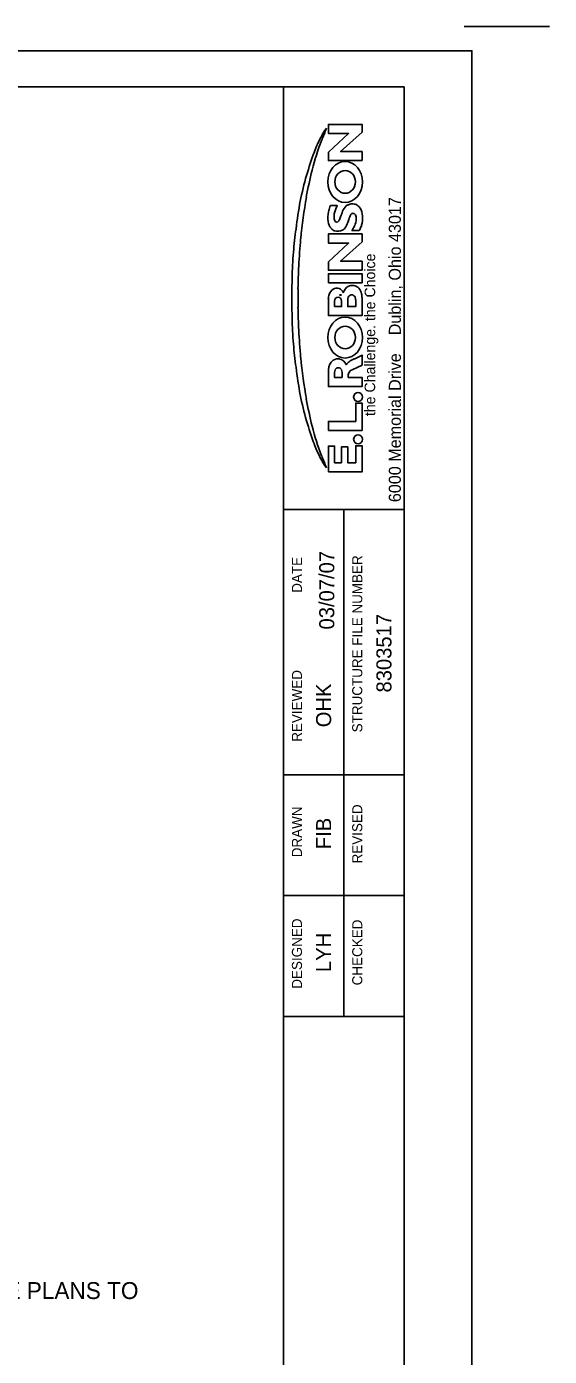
# Model space of a CAD drawing. Extents: x -70.8 to -34.9, y -11.1 to 10.9.
# Drawn here: x -39.19 to -34.86, y -0.16 to 10.86 of the extents above; entities that cross this region are included whole.
import ezdxf

# ---------------------------------------------------------------- set-up
doc = ezdxf.new("R2010")
doc.units = 0
for name, color, linetype in [('Default', 7, 'Continuous'), ('SH_Border', 7, 'Continuous'), ('SH_Cut_Line', 7, 'Continuous'), ('SH_Data', 7, 'Continuous')]:
    doc.layers.add(name, color=color, linetype=linetype)

msp = doc.modelspace()

# ---------------------------------------------------------------- linework, layer by layer
at = {"layer": 'Default'}
for p, q in [((-36.433, 9.166), (-36.494, 9.166)), ((-36.494, 9.166), (-36.433, 9.166)), ((-36.689, 8.462), (-36.689, 8.597)), ((-36.41, 8.612), (-36.41, 8.462)), ((-36.638, 8.583), (-36.638, 8.537)), ((-36.638, 8.537), (-36.638, 8.583)), ((-36.41, 8.462), (-36.689, 8.462)), ((-36.41, 8.052), (-36.492, 8.013)), ((-36.492, 8.013), (-36.41, 8.052)), ((-36.639, 7.992), (-36.639, 7.949)), ((-36.639, 7.949), (-36.639, 7.992)), ((-36.639, 7.949), (-36.575, 7.949)), ((-36.575, 7.949), (-36.639, 7.949)), ((-36.575, 7.949), (-36.575, 7.992)), ((-36.575, 7.992), (-36.575, 7.949))]:
    msp.add_line(p, q, dxfattribs=at)
for points in [[(-36.41, 9.746), (-36.689, 9.746), (-36.689, 9.815), (-36.521, 9.971), (-36.689, 9.971), (-36.689, 10.046), (-36.41, 10.046), (-36.41, 9.981), (-36.588, 9.82), (-36.41, 9.82)], [(-36.41, 8.838), (-36.689, 8.838), (-36.689, 8.907), (-36.521, 9.063), (-36.689, 9.063), (-36.689, 9.138), (-36.41, 9.138), (-36.41, 9.073), (-36.588, 8.912), (-36.41, 8.912)], [(-36.689, 8.734), (-36.689, 8.808), (-36.41, 8.808), (-36.41, 8.734)], [(-36.689, 7.167), (-36.689, 7.381), (-36.638, 7.381), (-36.638, 7.242), (-36.581, 7.242), (-36.581, 7.374), (-36.529, 7.374), (-36.529, 7.242), (-36.462, 7.242), (-36.462, 7.384), (-36.41, 7.384), (-36.41, 7.167)]]:
    msp.add_lwpolyline(points, close=True, dxfattribs=at)
for points in [[(-36.671, 9.373), (-36.616, 9.373), (-36.627, 9.346)], [(-36.627, 9.346), (-36.616, 9.373), (-36.671, 9.373)], [(-36.41, 8.612), (-36.41, 8.462), (-36.689, 8.462), (-36.689, 8.597)], [(-36.689, 8.597), (-36.689, 8.462), (-36.41, 8.462)], [(-36.41, 8.462), (-36.41, 8.612)], [(-36.638, 8.537), (-36.579, 8.537), (-36.579, 8.583)], [(-36.579, 8.583), (-36.579, 8.537), (-36.638, 8.537)], [(-36.528, 8.592), (-36.528, 8.537), (-36.462, 8.537), (-36.462, 8.592)], [(-36.462, 8.592), (-36.462, 8.537), (-36.528, 8.537), (-36.528, 8.592)], [(-36.475, 8.102), (-36.41, 8.134), (-36.41, 8.052)], [(-36.41, 8.052), (-36.41, 8.134), (-36.475, 8.102)], [(-36.524, 7.971), (-36.524, 7.949), (-36.41, 7.949), (-36.41, 7.874), (-36.689, 7.874), (-36.689, 7.949), (-36.689, 8.013)], [(-36.689, 8.013), (-36.689, 7.949), (-36.689, 7.874), (-36.41, 7.874)], [(-36.639, 7.992), (-36.639, 7.949), (-36.575, 7.949), (-36.575, 7.992)], [(-36.41, 7.874), (-36.41, 7.949), (-36.524, 7.949), (-36.524, 7.971)], [(-36.689, 7.51), (-36.689, 7.585), (-36.462, 7.585), (-36.462, 7.737), (-36.41, 7.737), (-36.41, 7.51), (-36.689, 7.51)], [(-36.41, 7.737), (-36.462, 7.737), (-36.462, 7.585), (-36.689, 7.585), (-36.689, 7.51)], [(-36.689, 7.51), (-36.41, 7.51), (-36.41, 7.737)]]:
    msp.add_lwpolyline(points, dxfattribs=at)
for centre, major_axis, ratio, start_param, end_param in [((-35.926, 9.339), (0, 1.141), 0.85, 0.988431, 1.105191), ((-35.926, 9.339), (0, 1.141), 0.85, 0.988431, 1.105191), ((-75.191, 31.113), (0, 49.953), 0.85, 4.274094, 4.276309), ((-75.191, 31.113), (0, 49.953), 0.85, 4.274094, 4.276309), ((-36.479, 9.767), (0, 0.363), 0.85, 0.822588, 0.988431), ((-36.479, 9.767), (0, 0.363), 0.85, 0.822588, 0.988431), ((-34.374, 8.593), (0, 3.112), 0.85, 1.165908, 1.233316), ((-34.374, 8.593), (0, 3.112), 0.85, 1.165908, 1.233316), ((-35.448, 9.198), (0, 1.685), 0.85, 1.132502, 1.288747), ((-35.448, 9.198), (0, 1.685), 0.85, 1.132502, 1.288747), ((-36.35, 9.589), (0, 0.583), 0.85, 1.105191, 1.165908), ((-36.35, 9.589), (0, 0.583), 0.85, 1.105191, 1.165908), ((-35.165, 8.941), (0, 2.119), 0.85, 1.243005, 1.347881), ((-35.165, 8.941), (0, 2.119), 0.85, 1.243005, 1.347881), ((-33.95, 8.688), (0, 3.52), 0.85, 1.288747, 1.354281), ((-33.95, 8.688), (0, 3.52), 0.85, 1.288747, 1.354281), ((-36.55, 9.569), (0, -0.0938), 0.910305, 4.71238898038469, 4.712389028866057), ((-33.976, 8.671), (0, 3.544), 0.85, 1.360764, 1.426378), ((-33.976, 8.671), (0, 3.544), 0.85, 1.360764, 1.426378), ((-32.731, 8.494), (0, 4.963), 0.85, 1.378198, 1.448475), ((-32.731, 8.494), (0, 4.963), 0.85, 1.378198, 1.448475), ((-36.81, 9.44), (0, 0.176), 0.85, 4.250261, 4.3216), ((-36.81, 9.44), (0, 0.176), 0.85, 4.250261, 4.3216), ((-36.486, 9.281), (0, 0.11), 0.85, 0.486829, 1.030221), ((-36.486, 9.281), (0, 0.11), 0.85, 0.486829, 1.030221), ((-36.55, 9.569), (0, -0.17), 0.841969, 0, 4.84813681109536e-08), ((-36.499, 9.31), (0, 0.0761), 0.85, 0.083326, 0.486829), ((-36.499, 9.31), (0, 0.0761), 0.85, 0.083326, 0.486829), ((-36.493, 9.233), (0, 0.154), 0.85, 6.083659, 6.366511), ((-36.493, 9.233), (0, 0.154), 0.85, 6.083659, 6.366511), ((-36.48, 9.311), (0, 0.0741), 0.85, 5.529173, 6.083659), ((-36.48, 9.311), (0, 0.0741), 0.85, 5.529173, 6.083659), ((-36.5, 9.286), (0, 0.109), 0.85, 4.887723, 5.529173), ((-36.5, 9.286), (0, 0.109), 0.85, 4.887723, 5.529174), ((-36.532, 9.273), (0, 0.19), 0.85, 1.320154, 1.737094), ((-36.532, 9.273), (0, 0.19), 0.85, 1.320154, 1.737094), ((-36.519, 9.27), (0, 0.206), 0.85, 1.108668, 1.320154), ((-36.519, 9.27), (0, 0.206), 0.85, 1.108668, 1.320154), ((-36.547, 9.282), (0, 0.111), 0.85, 1.456901, 1.818883), ((-36.547, 9.282), (0, 0.111), 0.85, 1.456901, 1.818883), ((-36.544, 9.282), (0, 0.115), 0.85, 1.297264, 1.456901), ((-36.544, 9.282), (0, 0.115), 0.85, 1.297264, 1.456901), ((-36.616, 9.262), (0, 0.0279), 0.85, 1.818883, 2.384672), ((-36.616, 9.262), (0, 0.0279), 0.85, 1.818883, 2.384672), ((-36.477, 9.26), (0, 0.196), 0.85, 1.114999, 1.297264), ((-36.477, 9.26), (0, 0.196), 0.85, 1.114999, 1.297264), ((-36.649, 9.292), (0, 0.071), 0.85, 4.01614, 4.175459), ((-36.649, 9.292), (0, 0.071), 0.85, 4.01614, 4.175459), ((-36.718, 9.34), (0, 0.165), 0.85, 4.175459, 4.396402), ((-36.718, 9.34), (0, 0.165), 0.85, 4.175459, 4.396402), ((-36.392, 9.215), (0, 0.238), 0.85, 1.030221, 1.254809), ((-36.392, 9.215), (0, 0.238), 0.85, 1.030221, 1.254809), ((-35.908, 8.96), (0, 0.778), 0.85, 1.164639, 1.211778), ((-35.908, 8.96), (0, 0.778), 0.85, 1.164639, 1.211778), ((-36.295, 9.156), (0, 0.284), 0.85, 1.063855, 1.164639), ((-36.295, 9.156), (0, 0.284), 0.85, 1.063855, 1.164639), ((-36.483, 9.279), (0, 0.0304), 0.85, 0.715581, 1.063855), ((-36.483, 9.279), (0, 0.0304), 0.85, 0.715581, 1.063855), ((-36.482, 9.278), (0, 0.0317), 0.85, 0.212074, 0.715581), ((-36.482, 9.278), (0, 0.0317), 0.85, 0.212074, 0.715581), ((-36.483, 9.283), (0, 0.026), 0.85, 5.247627, 6.495259), ((-36.483, 9.283), (0, 0.026), 0.85, 5.247627, 6.495259), ((-36.545, 9.264), (0, 0.103), 0.85, 4.251833, 4.86616), ((-36.545, 9.264), (0, 0.103), 0.85, 4.251833, 4.86616), ((-36.499, 9.272), (0, 0.0483), 0.85, 4.86616, 5.247627), ((-36.499, 9.272), (0, 0.0483), 0.85, 4.86616, 5.247627), ((-36.58, 9.269), (0, 0.205), 0.85, 4.51081, 4.887723), ((-36.58, 9.269), (0, 0.205), 0.85, 4.51081, 4.887723), ((-35.396, 8.848), (0, 1.866), 0.85, 1.391456, 1.496401), ((-35.396, 8.848), (0, 1.866), 0.85, 1.391456, 1.496401), ((-36.599, 9.26), (0, 0.11), 0.85, 1.737094, 2.325359), ((-36.599, 9.26), (0, 0.11), 0.85, 1.737094, 2.325359), ((-36.62, 9.237), (0, 0.0764), 0.85, 2.325359, 2.878408), ((-36.62, 9.237), (0, 0.0764), 0.85, 2.325359, 2.878408), ((-36.612, 9.273), (0, 0.113), 0.85, 2.878408, 3.55749), ((-36.612, 9.273), (0, 0.113), 0.85, 2.878408, 3.55749), ((-36.621, 9.256), (0, 0.0197), 0.85, 2.384672, 3.137191), ((-36.621, 9.256), (0, 0.0197), 0.85, 2.384672, 3.137191), ((-36.621, 9.264), (0, 0.0276), 0.85, 3.137191, 4.01614), ((-36.621, 9.264), (0, 0.0276), 0.85, 3.137191, 4.01614), ((-36.598, 9.237), (0, 0.0738), 0.85, 3.55749, 3.971659), ((-36.598, 9.237), (0, 0.0738), 0.85, 3.55749, 3.971659), ((-36.643, 9.285), (0, 0.145), 0.85, 3.971659, 4.353371), ((-36.643, 9.285), (0, 0.145), 0.85, 3.971659, 4.353371), ((-36.672, 9.328), (0, 0.265), 0.85, 4.050165, 4.172563), ((-36.672, 9.328), (0, 0.265), 0.85, 4.050165, 4.172563), ((-36.749, 9.382), (0, 0.37), 0.85, 4.172563, 4.251833), ((-36.749, 9.382), (0, 0.37), 0.85, 4.172563, 4.251833), ((-36.538, 9.255), (0, 0.152), 0.85, 4.087438, 4.318356), ((-36.538, 9.255), (0, 0.152), 0.85, 4.087438, 4.318356), ((-36.554, 9.263), (0, 0.173), 0.85, 4.318356, 4.51081), ((-36.554, 9.263), (0, 0.173), 0.85, 4.318356, 4.51081), ((-31.133, 8.427), (0, 6.84), 0.85, 1.472392, 1.505619), ((-31.133, 8.427), (0, 6.84), 0.85, 1.472392, 1.505619), ((-35.195, 8.747), (0, 2.111), 0.85, 1.456986, 1.558686), ((-35.195, 8.747), (0, 2.111), 0.85, 1.456986, 1.558686), ((-33.589, 8.616), (0, 3.944), 0.85, 1.505619, 1.553601), ((-33.589, 8.616), (0, 3.944), 0.85, 1.505619, 1.553601), ((-33.387, 8.554), (0, 4.243), 0.85, 1.519271, 1.558345), ((-33.387, 8.554), (0, 4.243), 0.85, 1.519271, 1.558345), ((-36.491, 8.614), (0, 0.0982), 0.85, 6.14188, 6.715345), ((-36.491, 8.614), (0, 0.0982), 0.85, 6.14188, 6.715345), ((-36.491, 8.614), (0, 0.0982), 0.85, 6.14188, 6.715345), ((-36.487, 8.623), (0, 0.0885), 0.85, 5.535543, 6.182102), ((-36.487, 8.623), (0, 0.0885), 0.85, 5.535543, 6.182102), ((-36.487, 8.623), (0, 0.0885), 0.85, 5.535543, 6.182102), ((-33.387, 8.66), (0, 4.243), 0.85, 1.583248, 1.622322), ((-33.387, 8.66), (0, 4.243), 0.85, 1.583248, 1.622322), ((-35.039, 8.645), (0, 2.237), 0.85, 1.553601, 1.587991), ((-35.039, 8.645), (0, 2.237), 0.85, 1.553601, 1.587991), ((-35.039, 8.568), (0, 2.237), 0.85, 1.553601, 1.587991), ((-35.039, 8.568), (0, 2.237), 0.85, 1.553601, 1.587991), ((-36.584, 8.595), (0, 0.124), 0.85, 1.228703, 1.558605), ((-36.584, 8.595), (0, 0.124), 0.85, 1.228703, 1.558605), ((-36.584, 8.595), (0, 0.124), 0.85, 1.228703, 1.558605), ((-36.617, 8.606), (0, 0.0833), 0.85, 0.473795, 1.194239), ((-36.617, 8.606), (0, 0.0833), 0.85, 0.473795, 1.194239), ((-36.617, 8.606), (0, 0.0833), 0.85, 0.473795, 1.194239), ((-36.62, 8.62), (0, 0.0696), 0.85, 5.943917, 6.808987), ((-36.62, 8.62), (0, 0.0696), 0.85, 5.943917, 6.808987), ((-36.62, 8.62), (0, 0.0696), 0.85, 5.943917, 6.808987), ((-36.61, 8.58), (0, 0.0337), 0.85, 6.249041, 7.784024), ((-36.61, 8.58), (0, 0.0337), 0.85, 6.249041, 7.784024), ((-36.608, 8.58), (0, 0.0337), 0.85, 4.782347, 6.317329), ((-36.608, 8.58), (0, 0.0337), 0.85, 4.782347, 6.317329), ((-36.622, 8.613), (0, 0.0776), 0.85, 5.231996, 5.947796), ((-36.622, 8.613), (0, 0.0776), 0.85, 5.231996, 5.947796), ((-36.622, 8.613), (0, 0.0776), 0.85, 5.231996, 5.947795), ((-36.492, 8.622), (0, 0.0906), 0.85, 0.462144, 1.247207), ((-36.492, 8.622), (0, 0.0906), 0.85, 0.462144, 1.247207), ((-36.492, 8.622), (0, 0.0906), 0.85, 0.462144, 1.247207), ((-36.494, 8.594), (0, 0.0402), 0.85, 0.503186, 1.629765), ((-36.494, 8.594), (0, 0.0402), 0.85, 0.503186, 1.629765), ((-36.495, 8.598), (0, 0.0358), 0.85, 6.277029, 6.794667), ((-36.495, 8.598), (0, 0.0358), 0.85, 6.277029, 6.794667), ((-36.495, 8.598), (0, 0.0358), 0.85, 5.771704, 6.289341), ((-36.495, 8.598), (0, 0.0358), 0.85, 5.771704, 6.289341), ((-36.497, 8.594), (0, 0.0402), 0.85, 4.65342, 5.779999), ((-36.497, 8.594), (0, 0.0402), 0.85, 4.65342, 5.779999), ((-36.482, 8.627), (0, 0.0818), 0.85, 4.885157, 5.560215), ((-36.482, 8.627), (0, 0.0818), 0.85, 4.885157, 5.560215), ((-36.482, 8.627), (0, 0.0818), 0.85, 4.885157, 5.560215), ((-36.582, 8.605), (0, 0.202), 0.85, 4.750784, 4.89449), ((-36.582, 8.605), (0, 0.202), 0.85, 4.750784, 4.89449), ((-36.582, 8.605), (0, 0.202), 0.85, 4.750784, 4.89449), ((-33.589, 8.598), (0, 3.944), 0.85, 1.587991, 1.635974), ((-33.589, 8.598), (0, 3.944), 0.85, 1.587991, 1.635974), ((-35.195, 8.467), (0, 2.111), 0.85, 1.582906, 1.684607), ((-35.195, 8.467), (0, 2.111), 0.85, 1.582906, 1.684607), ((-31.133, 8.786), (0, 6.84), 0.85, 1.635974, 1.669201), ((-31.133, 8.786), (0, 6.84), 0.85, 1.635974, 1.669201), ((-36.55, 8.28), (0, -0.0938), 0.910305, 4.71238898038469, 4.712389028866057), ((-35.396, 8.366), (0, 1.866), 0.85, 1.645192, 1.750137), ((-35.396, 8.366), (0, 1.866), 0.85, 1.645192, 1.750137), ((-32.731, 8.72), (0, 4.963), 0.85, 1.693118, 1.763395), ((-32.731, 8.72), (0, 4.963), 0.85, 1.693118, 1.763395), ((-36.613, 8.012), (0, 0.0895), 0.85, 0.482355, 1.561069), ((-36.613, 8.012), (0, 0.0895), 0.85, 0.482355, 1.561069), ((-36.608, 8.004), (0, 0.1), 0.85, 6.102437, 6.781247), ((-36.608, 8.004), (0, 0.1), 0.85, 6.102437, 6.781247), ((-36.609, 8.016), (0, 0.0881), 0.85, 5.152888, 6.061538), ((-36.609, 8.016), (0, 0.0881), 0.85, 5.152888, 6.061538), ((-36.55, 8.28), (0, -0.17), 0.841969, 0, 4.84813681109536e-08), ((-36.491, 8.017), (0, 0.069), 0.85, 0.463729, 1.012038), ((-36.491, 8.017), (0, 0.069), 0.85, 0.463729, 1.012038), ((-36.384, 7.805), (0, 0.316), 0.85, 0.346308, 0.520291), ((-36.384, 7.805), (0, 0.316), 0.85, 0.346308, 0.520291), ((-33.976, 8.543), (0, 3.544), 0.85, 1.715214, 1.780828), ((-33.976, 8.543), (0, 3.544), 0.85, 1.715214, 1.780828), ((-36.599, 7.988), (0, 0.0467), 0.85, 1.002734, 1.50285), ((-36.599, 7.988), (0, 0.0467), 0.85, 1.002734, 1.50285), ((-36.599, 7.988), (0, 0.0467), 0.85, 1.002734, 1.50285), ((-36.608, 7.992), (0, 0.0365), 0.85, 6.259044, 7.205975), ((-36.608, 7.992), (0, 0.0365), 0.85, 6.259044, 7.205975), ((-36.608, 7.992), (0, 0.0365), 0.85, 6.259044, 7.205975), ((-36.606, 7.992), (0, 0.0365), 0.85, 5.360396, 6.307326), ((-36.606, 7.992), (0, 0.0365), 0.85, 5.360396, 6.307326), ((-36.606, 7.992), (0, 0.0365), 0.85, 5.360396, 6.307326), ((-36.615, 7.988), (0, 0.0467), 0.85, 4.780335, 5.280452), ((-36.615, 7.988), (0, 0.0467), 0.85, 4.780335, 5.280452), ((-36.615, 7.988), (0, 0.0467), 0.85, 4.780335, 5.280452), ((-36.498, 7.972), (0, 0.0303), 0.85, 0.984544, 1.600686), ((-36.498, 7.972), (0, 0.0303), 0.85, 0.984544, 1.600686), ((-36.475, 7.952), (0, 0.0643), 0.85, 0.32473, 0.965239), ((-36.475, 7.952), (0, 0.0643), 0.85, 0.32473, 0.965239), ((-35.165, 8.273), (0, 2.119), 0.85, 1.793712, 1.898588), ((-35.165, 8.273), (0, 2.119), 0.85, 1.793712, 1.898588), ((-33.95, 8.526), (0, 3.52), 0.85, 1.787312, 1.852845), ((-33.95, 8.526), (0, 3.52), 0.85, 1.787312, 1.852845), ((-36.443, 7.787), (0, -0.0377), 0.965476, 4.71238898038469, 4.712389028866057), ((-34.374, 8.621), (0, 3.112), 0.85, 1.908276, 1.975684), ((-34.374, 8.621), (0, 3.112), 0.85, 1.908276, 1.975684), ((-35.448, 8.015), (0, 1.685), 0.85, 1.852845, 2.009091), ((-35.448, 8.015), (0, 1.685), 0.85, 1.852845, 2.009091), ((-36.35, 7.624), (0, 0.583), 0.85, 1.975684, 2.036401), ((-36.35, 7.624), (0, 0.583), 0.85, 1.975684, 2.036401), ((-36.443, 7.437), (0, -0.0377), 0.965476, 4.71238898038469, 4.712389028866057), ((-35.926, 7.875), (0, 1.141), 0.85, 2.036401, 2.153161), ((-35.926, 7.875), (0, 1.141), 0.85, 2.036401, 2.153161), ((-75.191, -13.899), (0, 49.953), 0.85, 5.148469, 5.150684), ((-75.191, -13.899), (0, 49.953), 0.85, 5.148469, 5.150684), ((-36.479, 7.447), (0, 0.363), 0.85, 2.153161, 2.319004), ((-36.479, 7.447), (0, 0.363), 0.85, 2.153161, 2.319004)]:
    msp.add_ellipse(centre, major_axis=major_axis, ratio=ratio, start_param=start_param, end_param=end_param, dxfattribs=at)
for centre, major_axis, ratio in [((-36.55, 9.569), (0, -0.17), 0.841969), ((-36.55, 9.569), (0, -0.17), 0.841969), ((-36.55, 9.569), (0, -0.0938), 0.910305), ((-36.55, 9.569), (0, -0.0938), 0.910305), ((-36.55, 8.28), (0, -0.17), 0.841969), ((-36.55, 8.28), (0, -0.17), 0.841969), ((-36.55, 8.28), (0, -0.0938), 0.910305), ((-36.55, 8.28), (0, -0.0938), 0.910305), ((-36.443, 7.787), (0, -0.0377), 0.965476), ((-36.443, 7.437), (0, -0.0377), 0.965476), ((-36.443, 7.437), (0, -0.0377), 0.965476)]:
    msp.add_ellipse(centre, major_axis=major_axis, ratio=ratio, dxfattribs=at)
at = {"layer": 'SH_Border'}
for p, q in [((-37.062, -10.644), (-37.062, 10.356)), ((-37.062, 6.856), (-36.062, 6.856)), ((-36.562, 2.656), (-36.562, 6.856)), ((-37.062, 4.656), (-36.062, 4.656)), ((-37.062, 3.656), (-36.062, 3.656)), ((-37.062, 2.656), (-36.062, 2.656))]:
    msp.add_line(p, q, dxfattribs=at)
msp.add_lwpolyline([(-67.562, 10.356), (-36.062, 10.356), (-36.062, -10.644), (-67.562, -10.644)], close=True, dxfattribs=at)
at = {"layer": 'SH_Cut_Line'}
msp.add_line((-35.562, 10.856), (-34.857, 10.856), dxfattribs=at)
msp.add_lwpolyline([(-35.499, -10.994), (-69.499, -10.994), (-69.499, 10.656), (-35.499, 10.656)], close=True, dxfattribs=at)

# ---------------------------------------------------------------- texts
at = {"layer": 'Default'}
for s, height, p in [('6000 Memorial Drive    Dublin, Ohio 43017', 0.1, (-36.088, 6.916)), ('the Challenge. the Choice', 0.0875, (-36.301, 7.629))]:
    msp.add_text(s, height=height, rotation=90, dxfattribs=at).set_placement(p)
at = {"layer": 'SH_Data'}
for s, height, p in [('.', 0.125, (-36.579, 8.61)), ("'", 0.125, (-36.245, 8.61)), ('03/07/07', 0.125, (-36.64, 5.861)), ('DATE', 0.0833, (-36.908, 6.165)), ('STRUCTURE FILE NUMBER', 0.0833, (-36.408, 5.009)), ('8303517', 0.125, (-36.166, 5.339)), ('REVIEWED', 0.0833, (-36.908, 4.931)), ('OHK', 0.125, (-36.666, 5.051)), ('DRAWN', 0.0833, (-36.908, 3.974)), ('REVISED', 0.0833, (-36.408, 3.923)), ('FIB', 0.125, (-36.666, 4.041)), ('DESIGNED', 0.0833, (-36.908, 2.885)), ('CHECKED', 0.0833, (-36.408, 2.913)), ('LYH', 0.125, (-36.666, 3.023))]:
    msp.add_text(s, height=height, rotation=90, dxfattribs=at).set_placement(p)
msp.add_text('THE FOLLOWING ABBREVIATIONS HAVE BEEN USED THROUGHOUT THESE PLANS TO', height=0.14, dxfattribs=at).set_placement((-46.117, 0.314))

doc.saveas('drawing.dxf')
